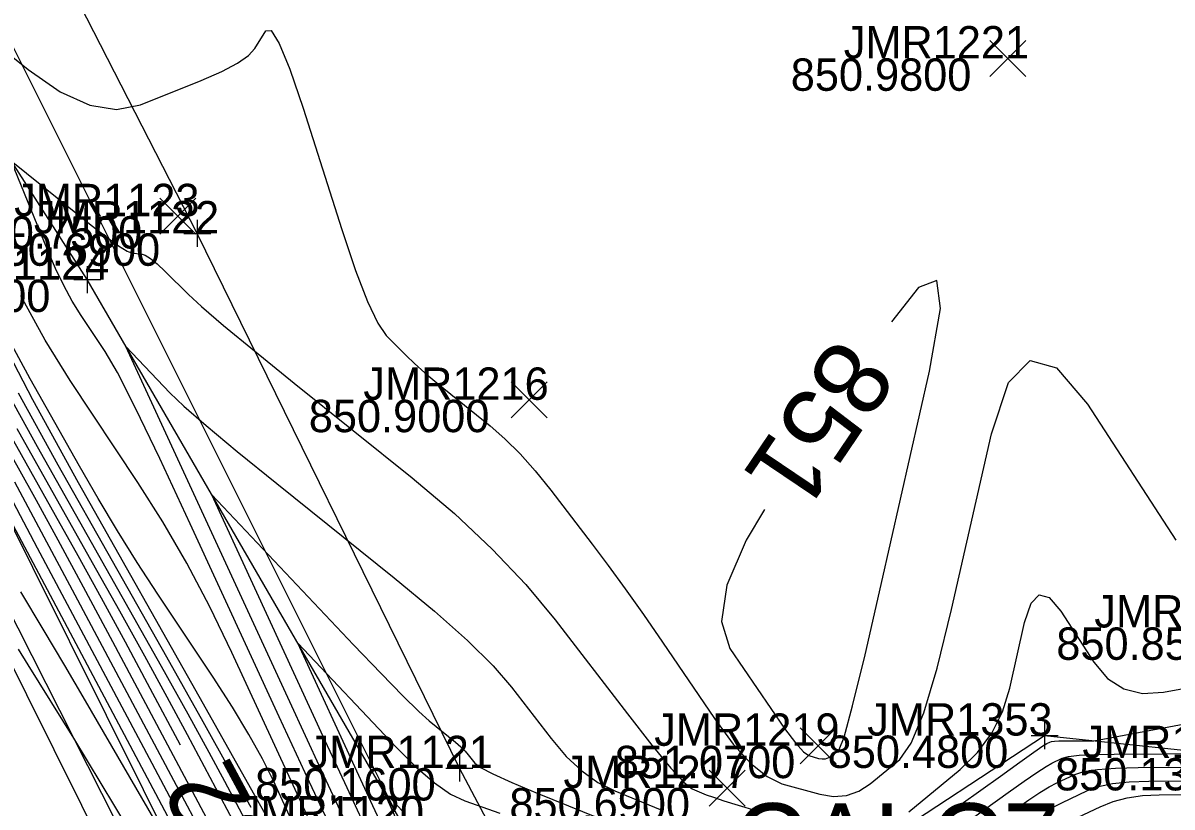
# Model space of a CAD drawing. Extents: x 1654928 to 1810050, y 486881 to 626330.
# Drawn here: x 1801428.02 to 1801470.61, y 489847.53 to 489876.6 of the extents above; entities that cross this region are included whole.
import ezdxf

# ---------------------------------------------------------------- set-up
doc = ezdxf.new("R2010")
doc.units = 0
for name, color, linetype in [('DR_X_Ditch', 7, 'Continuous'), ('DT_X_Contour_Major', 7, 'Continuous'), ('DT_X_Contour_Minor', 7, 'Continuous'), ('GK_Visualization', 7, 'Continuous'), ('PV_X_EOP', 7, 'Continuous'), ('PV_X_Shoulder', 7, 'Continuous'), ('RD_X_Fence', 7, 'Continuous'), ('RW_X_Esmt_SH', 7, 'Continuous'), ('SV_X_Break_Lines', 7, 'Continuous'), ('SV_X_Random_Point', 7, 'Continuous'), ('SV_X_Shot_Marker', 7, 'Continuous'), ('SV_X_Text_Elevation', 7, 'Continuous'), ('SV_X_Text_Name', 7, 'Continuous'), ('SV_X_Top_of_Bank', 7, 'Continuous')]:
    doc.layers.add(name, color=color, linetype=linetype)

msp = doc.modelspace()

# ---------------------------------------------------------------- linework, layer by layer
at = {"layer": 'DR_X_Ditch'}
msp.add_lwpolyline([(1801442.185, 489846.735), (1801430.401, 489867.086), (1801416.556, 489888.735), (1801414.305, 489897.031)], dxfattribs=at)
at = {"layer": 'DT_X_Contour_Major'}
for points in [[(1801419.949, 489876.892), (1801420.818, 489875.143), (1801421.603, 489873.509), (1801422.304, 489871.987), (1801424.06, 489868.082), (1801424.74, 489866.618), (1801425.46, 489865.156), (1801426.221, 489863.696), (1801427.023, 489862.238), (1801429.216, 489858.352), (1801430.051, 489856.858), (1801430.914, 489855.292), (1801431.803, 489853.653), (1801432.719, 489851.942), (1801433.839, 489849.834)], [(1801458.275, 489849.668), (1801458.452, 489850.116), (1801458.77, 489851.283), (1801459.229, 489853.171), (1801459.83, 489855.778), (1801461.62, 489863.69), (1801462.023, 489866.014), (1801461.886, 489867.05), (1801461.211, 489866.799), (1801460.206, 489865.525)], [(1801438.249, 489846.447), (1801437.306, 489848.495), (1801436.901, 489849.311), (1801436.392, 489850.224), (1801435.779, 489851.235), (1801435.063, 489852.344), (1801433.015, 489855.428), (1801432.257, 489856.592), (1801431.52, 489857.771), (1801430.804, 489858.964), (1801430.108, 489860.171), (1801428.281, 489863.409), (1801427.532, 489864.802)], [(1801455.508, 489858.564), (1801454.818, 489857.431), (1801454.105, 489855.755), (1801453.904, 489854.414), (1801454.216, 489853.41), (1801455.732, 489851.182), (1801456.247, 489850.446), (1801456.654, 489849.909), (1801456.952, 489849.572), (1801457.143, 489849.435), (1801457.507, 489849.333), (1801457.64, 489849.311), (1801457.765, 489849.32), (1801457.882, 489849.361), (1801457.992, 489849.433), (1801458.275, 489849.668)], [(1801433.844, 489845.427), (1801430.332, 489851.464), (1801429.565, 489852.776), (1801428.768, 489854.125), (1801427.942, 489855.511)], [(1801441.337, 489846.83), (1801440.988, 489847.571), (1801440.539, 489848.542), (1801438.204, 489853.61), (1801441.85, 489849.751), (1801442.595, 489849.007), (1801443.267, 489848.426), (1801443.866, 489848.01), (1801444.392, 489847.758), (1801445.698, 489847.306)], [(1801464.832, 489847.462), (1801465.303, 489847.792), (1801465.711, 489848.063), (1801466.056, 489848.272), (1801466.339, 489848.422), (1801467.008, 489848.74), (1801467.343, 489848.845), (1801467.846, 489848.921), (1801468.518, 489848.969), (1801469.357, 489848.989), (1801471.82, 489849.005)]]:
    msp.add_lwpolyline(points, dxfattribs=at)
at = {"layer": 'DT_X_Contour_Minor'}
for points in [[(1801422.453, 489879.514), (1801428.216, 489874.874), (1801429.402, 489874.046), (1801430.491, 489873.552), (1801431.481, 489873.392), (1801432.375, 489873.566), (1801434.626, 489874.475), (1801435.384, 489874.804), (1801435.968, 489875.111), (1801436.38, 489875.394), (1801436.618, 489875.654), (1801437.022, 489876.318), (1801437.222, 489876.325), (1801437.519, 489875.848), (1801437.913, 489874.887), (1801438.404, 489873.441), (1801439.842, 489868.942), (1801440.349, 489867.431), (1801440.79, 489866.273), (1801441.167, 489865.466), (1801441.479, 489865.012), (1801442.224, 489864.272), (1801442.536, 489863.974), (1801442.916, 489863.635), (1801443.362, 489863.256), (1801443.876, 489862.836), (1801445.334, 489861.663), (1801445.884, 489861.184), (1801446.442, 489860.628), (1801447.008, 489859.993), (1801447.581, 489859.281), (1801449.119, 489857.277), (1801449.714, 489856.487), (1801450.345, 489855.618), (1801451.014, 489854.672), (1801451.719, 489853.648), (1801453.647, 489850.813), (1801454.346, 489849.865), (1801454.996, 489849.145), (1801455.596, 489848.655), (1801456.147, 489848.394), (1801457.552, 489848.004), (1801458.064, 489847.918), (1801458.547, 489847.954), (1801459, 489848.111), (1801459.424, 489848.389), (1801460.515, 489849.294), (1801460.942, 489849.896), (1801461.405, 489851.024), (1801461.904, 489852.677), (1801462.438, 489854.856), (1801463.912, 489861.366), (1801464.549, 489863.266), (1801465.355, 489864.083), (1801466.33, 489863.817), (1801467.474, 489862.468), (1801470.75, 489857.426)], [(1801419.5, 489876.695), (1801420.609, 489874.538), (1801421.538, 489872.695), (1801422.285, 489871.166), (1801422.851, 489869.952), (1801424.12, 489867.131), (1801424.61, 489866.074), (1801425.131, 489865.018), (1801425.68, 489863.964), (1801426.259, 489862.911), (1801427.843, 489860.104), (1801428.507, 489858.912), (1801429.309, 489857.443), (1801430.251, 489855.696), (1801431.332, 489853.671), (1801434.399, 489847.901), (1801435.435, 489845.956), (1801436.243, 489844.448), (1801436.822, 489843.379), (1801437.172, 489842.747), (1801437.802, 489841.646), (1801438.026, 489841.253)], [(1801439.532, 489846.557), (1801438.638, 489848.447), (1801437.514, 489850.869), (1801434.213, 489858.034), (1801433.089, 489860.448), (1801432.189, 489862.316), (1801431.516, 489863.639), (1801431.068, 489864.416), (1801430.175, 489865.761), (1801429.846, 489866.291), (1801429.529, 489866.872), (1801429.223, 489867.504), (1801428.928, 489868.188), (1801427.581, 489871.496), (1801430.549, 489869.106), (1801431.121, 489868.657), (1801431.565, 489868.334), (1801431.881, 489868.137), (1801432.068, 489868.066), (1801432.397, 489868.045), (1801432.546, 489867.998), (1801432.744, 489867.872), (1801432.992, 489867.669), (1801433.289, 489867.387), (1801434.149, 489866.532), (1801434.637, 489866.086), (1801435.453, 489865.391), (1801436.6, 489864.446), (1801438.075, 489863.251), (1801442.45, 489859.731), (1801444.011, 489858.413), (1801445.413, 489857.097), (1801446.657, 489855.783), (1801447.742, 489854.472), (1801450.423, 489850.979), (1801451.327, 489849.822), (1801452.028, 489848.974), (1801452.528, 489848.433), (1801452.825, 489848.2), (1801453.347, 489847.987), (1801453.608, 489847.891), (1801454, 489847.762), (1801454.523, 489847.6), (1801455.176, 489847.404)], [(1801438.628, 489847.06), (1801437.882, 489848.658), (1801435.76, 489853.264), (1801434.946, 489854.953), (1801434.094, 489856.566), (1801433.206, 489858.102), (1801432.281, 489859.561), (1801429.765, 489863.352), (1801428.837, 489864.845), (1801427.942, 489866.483)], [(1801437.332, 489846.688), (1801436.23, 489848.642), (1801434.705, 489851.344), (1801430.076, 489859.548), (1801428.383, 489862.626), (1801426.776, 489865.709)], [(1801439.979, 489846.983), (1801439.074, 489848.91), (1801437.905, 489851.434), (1801431.834, 489864.611), (1801433.465, 489862.885), (1801433.975, 489862.397), (1801434.805, 489861.674), (1801435.955, 489860.716), (1801437.425, 489859.522), (1801441.773, 489856.023), (1801443.269, 489854.786), (1801444.493, 489853.698), (1801445.447, 489852.76), (1801446.131, 489851.971), (1801447.593, 489850.065), (1801448.152, 489849.408), (1801448.731, 489848.866), (1801449.331, 489848.437), (1801449.952, 489848.124), (1801451.634, 489847.44)], [(1801427.302, 489863.161), (1801428.549, 489860.893), (1801431.96, 489854.848), (1801433.141, 489852.75), (1801434.123, 489850.99), (1801434.907, 489849.568), (1801435.492, 489848.483), (1801436.79, 489846.042)], [(1801427.842, 489862.894), (1801429.312, 489860.221), (1801433.333, 489853.096), (1801434.685, 489850.696), (1801435.727, 489848.839), (1801436.459, 489847.525)], [(1801427.786, 489861.566), (1801430.588, 489856.6), (1801431.596, 489854.804), (1801432.518, 489853.141), (1801433.355, 489851.61), (1801434.105, 489850.213), (1801435.993, 489846.662)], [(1801434.215, 489846.491), (1801432.805, 489849.14), (1801428.558, 489857.13), (1801427.147, 489859.782)], [(1801427.705, 489859.594), (1801428.699, 489857.739), (1801429.945, 489855.4), (1801433.602, 489848.52), (1801434.825, 489846.224)], [(1801434.189, 489845.659), (1801433.048, 489847.804), (1801427.009, 489859.164)], [(1801440.658, 489846.907), (1801440.031, 489848.24), (1801439.222, 489849.988), (1801435.019, 489859.111), (1801440.274, 489853.549), (1801441.293, 489852.479), (1801442.099, 489851.652), (1801442.691, 489851.069), (1801443.07, 489850.728), (1801443.794, 489850.145), (1801444.044, 489849.939), (1801444.248, 489849.758), (1801444.407, 489849.601), (1801444.521, 489849.47), (1801444.764, 489849.152), (1801444.978, 489848.994), (1801445.434, 489848.757), (1801446.135, 489848.442), (1801447.079, 489848.048), (1801449.921, 489846.892)], [(1801460.855, 489847.345), (1801462.755, 489848.92), (1801463.404, 489849.551), (1801463.927, 489850.264), (1801464.324, 489851.058), (1801464.594, 489851.933), (1801465.146, 489854.374), (1801465.385, 489855.087), (1801465.688, 489855.393), (1801466.053, 489855.293), (1801466.482, 489854.787), (1801467.711, 489852.897), (1801468.218, 489852.296), (1801468.818, 489851.91), (1801469.511, 489851.741), (1801470.296, 489851.787), (1801472.515, 489852.198)], [(1801431.757, 489847.002), (1801431.426, 489847.555), (1801429.903, 489850.078), (1801428.21, 489852.798), (1801427.848, 489853.379)], [(1801462.069, 489847.11), (1801464.246, 489848.674), (1801464.966, 489849.189), (1801465.492, 489849.563), (1801465.824, 489849.795), (1801465.963, 489849.886), (1801466.074, 489849.939), (1801466.14, 489849.956), (1801466.253, 489849.969), (1801466.414, 489849.978), (1801466.623, 489849.982), (1801467.708, 489849.988), (1801472.14, 489850.809)], [(1801462.78, 489846.805), (1801464.539, 489848.068), (1801465.134, 489848.491), (1801465.601, 489848.813), (1801465.94, 489849.034), (1801466.151, 489849.154), (1801466.541, 489849.339), (1801466.771, 489849.401), (1801467.168, 489849.446), (1801467.731, 489849.475), (1801468.462, 489849.488), (1801472.26, 489849.512)], [(1801466.172, 489847.511), (1801466.527, 489847.69), (1801467.475, 489848.14), (1801467.884, 489848.288), (1801468.398, 489848.396), (1801469.019, 489848.462), (1801469.745, 489848.487), (1801471.823, 489848.5)], [(1801441.856, 489847.096), (1801441.389, 489848.11), (1801442.118, 489847.338)], [(1801466.715, 489846.958), (1801467.942, 489847.54), (1801468.424, 489847.732), (1801468.95, 489847.87), (1801469.519, 489847.954), (1801470.133, 489847.985), (1801471.826, 489847.996)]]:
    msp.add_lwpolyline(points, dxfattribs=at)
at = {"layer": 'PV_X_EOP'}
msp.add_lwpolyline([(1801533.684, 489642.188), (1801522.484, 489664.508), (1801511.881, 489685.341), (1801500.299, 489708.684), (1801491.104, 489726.659), (1801480.832, 489747.383), (1801466.882, 489774.659), (1801456.506, 489795.715), (1801444.637, 489819.009), (1801433.258, 489841.444), (1801422.029, 489863.995), (1801410.905, 489885.928), (1801399.817, 489908.089), (1801388.576, 489930.656), (1801376.228, 489955.188), (1801366.008, 489975.62), (1801354.725, 489997.894)], dxfattribs=at)
at = {"layer": 'PV_X_Shoulder'}
msp.add_lwpolyline([(1801534.471, 489642.456), (1801522.963, 489664.954), (1801512.6, 489685.485), (1801500.973, 489709.112), (1801491.766, 489727.019), (1801481.526, 489747.768), (1801467.484, 489775.07), (1801457.116, 489796.092), (1801445.57, 489819.398), (1801434.029, 489841.927), (1801422.682, 489864.343), (1801411.885, 489886.25), (1801400.664, 489908.455), (1801366.703, 489976.232), (1801355.676, 489998.276)], dxfattribs=at)
at = {"layer": 'RD_X_Fence'}
msp.add_lwpolyline([(1801551.601, 489647.601), (1801542.924, 489663.468), (1801525.109, 489695.967), (1801509.688, 489725.543), (1801495.067, 489753.216), (1801479.522, 489782.185), (1801467.623, 489805.516), (1801461.848, 489815.569), (1801444.198, 489848.97), (1801434.479, 489868.8), (1801422.196, 489892.762), (1801414.797, 489907.008)], dxfattribs=at)
at = {"layer": 'RW_X_Esmt_SH'}
msp.add_line((1801569.151, 489592.806), (1801345.762, 490039.449), dxfattribs=at)
at = {"layer": 'SV_X_Break_Lines'}
msp.add_lwpolyline([(1801445.791, 489822.136), (1801441.193, 489830.46), (1801435.211, 489842.68), (1801424.275, 489864.659), (1801412.811, 489886.984), (1801408.709, 489897.161), (1801400.001, 489913.183), (1801395.188, 489923.674), (1801385.653, 489941.642), (1801375.001, 489962.91), (1801364.942, 489983.144), (1801355.514, 490001.536)], dxfattribs=at)
at = {"layer": 'SV_X_Random_Point'}
for p, q in [((1801463.86, 489874.621), (1801465.193, 489875.956)), ((1801463.86, 489875.956), (1801465.193, 489874.621)), ((1801433.091, 489868.771), (1801434.424, 489870.106)), ((1801433.091, 489870.106), (1801434.424, 489868.771)), ((1801446.109, 489861.962), (1801447.442, 489863.297)), ((1801446.109, 489863.297), (1801447.442, 489861.962)), ((1801456.824, 489849.131), (1801458.158, 489850.466)), ((1801456.824, 489850.466), (1801458.158, 489849.131)), ((1801453.451, 489847.566), (1801454.784, 489848.901)), ((1801453.451, 489848.901), (1801454.784, 489847.566))]:
    msp.add_line(p, q, dxfattribs=at)
at = {"layer": 'SV_X_Shot_Marker'}
for p, q in [((1801434.479, 489869.3), (1801434.479, 489868.3)), ((1801433.979, 489868.8), (1801434.979, 489868.8)), ((1801434.479, 489868.8), (1801434.479, 489868.8)), ((1801430.401, 489867.586), (1801430.401, 489866.586)), ((1801429.901, 489867.086), (1801430.901, 489867.086)), ((1801430.401, 489867.086), (1801430.401, 489867.086)), ((1801465.887, 489850.679), (1801465.887, 489849.679)), ((1801465.387, 489850.179), (1801466.387, 489850.179)), ((1801465.887, 489850.179), (1801465.887, 489850.179)), ((1801444.198, 489849.47), (1801444.198, 489848.47)), ((1801443.698, 489848.97), (1801444.698, 489848.97)), ((1801444.198, 489848.97), (1801444.198, 489848.97))]:
    msp.add_line(p, q, dxfattribs=at)
at = {"layer": 'SV_X_Top_of_Bank'}
msp.add_lwpolyline([(1801452.193, 489836.758), (1801459.513, 489846.009), (1801465.887, 489850.179), (1801473.853, 489849.345), (1801479.986, 489850.885), (1801482.71, 489854.488), (1801486.035, 489852.905), (1801488.583, 489850.107), (1801492.084, 489852.448), (1801498.522, 489852.672), (1801506.396, 489853.841), (1801518.285, 489853.998), (1801520.681, 489853.368), (1801531.615, 489850.939), (1801557.484, 489854.39)], dxfattribs=at)

# ---------------------------------------------------------------- texts
at = {"layer": 'DT_X_Contour_Major'}
for s, rotation, p in [('851', 235.9847, (1801458.153, 489865.053)), ('852', 118.323, (1801438.551, 489843.996))]:
    msp.add_text(s, height=2.8, rotation=rotation, dxfattribs=at).set_placement(p)
at = {"layer": 'GK_Visualization'}
msp.add_text('CALC7', height=2.8, dxfattribs=at).set_placement((1801454.361, 489844.868))
at = {"layer": 'SV_X_Text_Elevation'}
for s, p in [('850.9800', (1801456.477, 489874.089)), ('850.7500', (1801425.745, 489868.239)), ('850.6900', (1801426.411, 489867.6)), ('850.4900', (1801422.342, 489865.886)), ('850.9000', (1801438.613, 489861.429)), ('850.8500', (1801466.32, 489852.987)), ('850.4800', (1801457.847, 489848.979)), ('851.0700', (1801449.952, 489848.599)), ('850.1300', (1801466.276, 489848.145)), ('850.1600', (1801436.622, 489847.77)), ('850.6900', (1801446.049, 489847.034))]:
    msp.add_text(s, height=1.2, dxfattribs=at).set_placement(p)
at = {"layer": 'SV_X_Text_Name'}
for s, p in [('JMR1221', (1801458.442, 489875.289)), ('JMR1123', (1801427.693, 489869.439)), ('JMR1122', (1801428.424, 489868.8)), ('JMR1124', (1801424.346, 489867.086)), ('JMR1216', (1801440.636, 489862.629)), ('JMR1220', (1801467.729, 489854.187)), ('JMR1353', (1801459.312, 489850.179)), ('JMR1219', (1801451.417, 489849.799)), ('JMR1121', (1801438.568, 489848.97)), ('JMR1354', (1801467.287, 489849.345)), ('JMR1217', (1801448.053, 489848.234)), ('JMR1120', (1801436.017, 489846.735))]:
    msp.add_text(s, height=1.2, dxfattribs=at).set_placement(p)

doc.saveas('drawing.dxf')
